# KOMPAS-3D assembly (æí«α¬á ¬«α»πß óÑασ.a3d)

Referenced files in D:\МОДЕЛЬ ТАНКА Т90\ДЕТАЛИ\КОРПУС\МЕТАЛЛ\КОРПУС ЛИТОЙ\: корпус верх.m3d, люк механника.m3d
Referenced files in D:\МОДЕЛЬ ТАНКА Т90\ДЕТАЛИ\КОРПУС\МЕТАЛЛ\КОРПУС ШТАМПОВКА\ПЛАСТИК\: корпус верх пластик.m3d
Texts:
  Сборка корпус верх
